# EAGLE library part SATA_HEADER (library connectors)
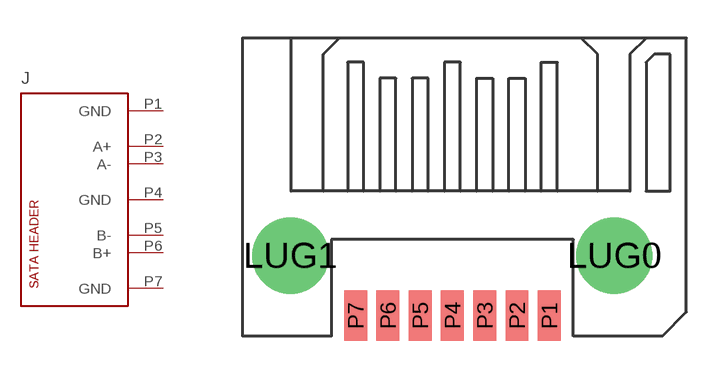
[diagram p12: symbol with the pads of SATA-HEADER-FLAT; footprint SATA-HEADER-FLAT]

Designator prefix J

## SATA_HEADER  [SATA-HEADER-FLAT]
P1  GND  pwr
P2  A+
P3  A-
P4  GND  pwr
P5  B-
P6  B+
P7  GND  pwr

## Footprint SATA-HEADER-FLAT (pad centres in mm)
drill 1.75 pad 3 round: LUG0 6.37,0; LUG1 -6.37,0
smd 0.9 x 2: P1 3.81,-2.36; P2 2.54,-2.36; P3 1.27,-2.36; P4 0,-2.36; P5 -1.27,-2.36; P6 -2.54,-2.36; P7 -3.81,-2.36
